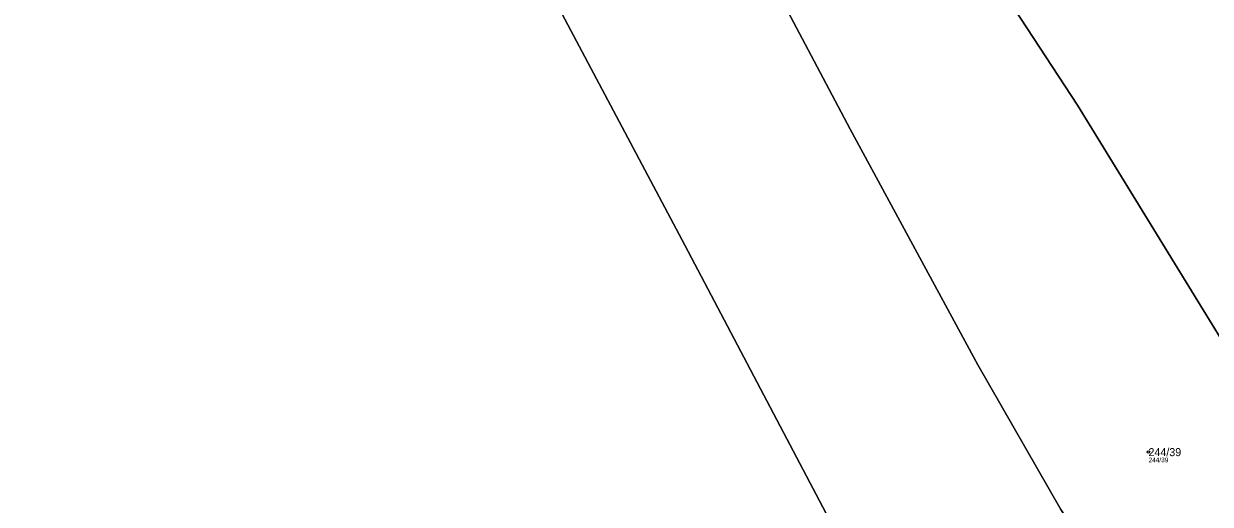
# Model space of a CAD drawing. Extents: x -734504 to -730695, y -1027923 to -1024502.
# Drawn here: x -732908.7 to -732656.7, y -1026758 to -1026655.8 of the extents above; entities that cross this region are included whole.
import ezdxf

# ---------------------------------------------------------------- set-up
doc = ezdxf.new("R2010")
doc.units = 0
for name, color, linetype in [('Definiční body', 7, 'Continuous'), ('Hranice parcel', 7, 'Continuous'), ('Parcelní čísla', 7, 'Continuous'), ('Polygon parcely', 7, 'Continuous')]:
    doc.layers.add(name, color=color, linetype=linetype)

msp = doc.modelspace()

# ---------------------------------------------------------------- linework, layer by layer
at = {"layer": 'Definiční body'}
msp.add_circle((-732669.79, -1026746.91), 0.25, dxfattribs=at)
at = {"layer": 'Hranice parcel'}
for points in [[(-732721.49, -1026616.73), (-732711.79, -1026631.97), (-732684.86, -1026673.13), (-732649.36, -1026730.99), (-732623.49, -1026773.22), (-732615.69, -1026785.9)], [(-732616.62, -1026889.29), (-732632.55, -1026858.35), (-732648.6, -1026827.92), (-732667.97, -1026790.88), (-732688.4, -1026759.09), (-732706.02, -1026728.33), (-732733.16, -1026678.24), (-732754.11, -1026638.56)], [(-732654.56, -1026909.04), (-732679.68, -1026866.19), (-732701.67, -1026826.77), (-732729.19, -1026777.15), (-732768.3, -1026702.94), (-732798.61, -1026645.74)]]:
    msp.add_lwpolyline(points, dxfattribs=at)
at = {"layer": 'Polygon parcely'}
for points in [[(-732639.06, -1026468.66), (-732659.3, -1026481.17), (-732685.7, -1026499.09), (-732711.86, -1026521.34), (-732717.84, -1026528.05), (-732689.62, -1026560.57), (-732697.65, -1026586.67), (-732696.81, -1026592.46), (-732701.31, -1026600.71), (-732709.81, -1026608.52), (-732721.49, -1026616.73), (-732711.79, -1026631.97), (-732684.86, -1026673.13), (-732649.36, -1026730.99)], [(-732729.19, -1026777.15), (-732768.3, -1026702.94), (-732798.61, -1026645.74), (-732800.93, -1026644.46), (-732827.14, -1026622.45), (-732846.74, -1026614.02), (-732856.1, -1026616.62), (-732879.43, -1026624.49), (-732902.39, -1026632.89), (-732932.66, -1026638.06), (-732950.63, -1026641.96), (-732969.54, -1026645.58), (-732984.59, -1026649.74), (-733001.87, -1026663.47), (-733003.3, -1026664.63), (-733000.81, -1026667.77), (-732989.8, -1026683.48), (-732975.93, -1026705.96), (-732967.96, -1026744.62), (-732973.12, -1026763.92)]]:
    msp.add_lwpolyline(points, dxfattribs=at)
for points in [[(-732569.73, -1026865.47), (-732598.04, -1026816.63), (-732614.07, -1026788.65), (-732615.69, -1026785.9), (-732623.49, -1026773.22), (-732649.36, -1026730.99), (-732684.86, -1026673.13), (-732711.79, -1026631.97), (-732721.49, -1026616.73), (-732733.16, -1026624.95), (-732754.11, -1026638.56), (-732733.16, -1026678.24), (-732706.02, -1026728.33), (-732688.4, -1026759.09), (-732667.97, -1026790.88), (-732648.6, -1026827.92), (-732632.55, -1026858.35), (-732616.62, -1026889.29), (-732584.41, -1026871.87)], [(-732667.97, -1026790.88), (-732688.4, -1026759.09), (-732706.02, -1026728.33), (-732733.16, -1026678.24), (-732754.11, -1026638.56), (-732767.08, -1026646.98), (-732784.1, -1026653.74), (-732798.61, -1026645.74), (-732768.3, -1026702.94), (-732729.19, -1026777.15), (-732701.67, -1026826.77), (-732679.68, -1026866.19), (-732654.56, -1026909.04), (-732649.46, -1026907.06), (-732616.62, -1026889.29), (-732632.55, -1026858.35), (-732648.6, -1026827.92)]]:
    msp.add_lwpolyline(points, close=True, dxfattribs=at)

# ---------------------------------------------------------------- texts
at = {"layer": 'Definiční body'}
msp.add_text('244/39', height=1, dxfattribs=at).set_placement((-732669.79, -1026749.07))
at = {"layer": 'Parcelní čísla'}
msp.add_text('244/39', height=1.7, dxfattribs=at).set_placement((-732669.79, -1026747.76))

doc.saveas('drawing.dxf')
